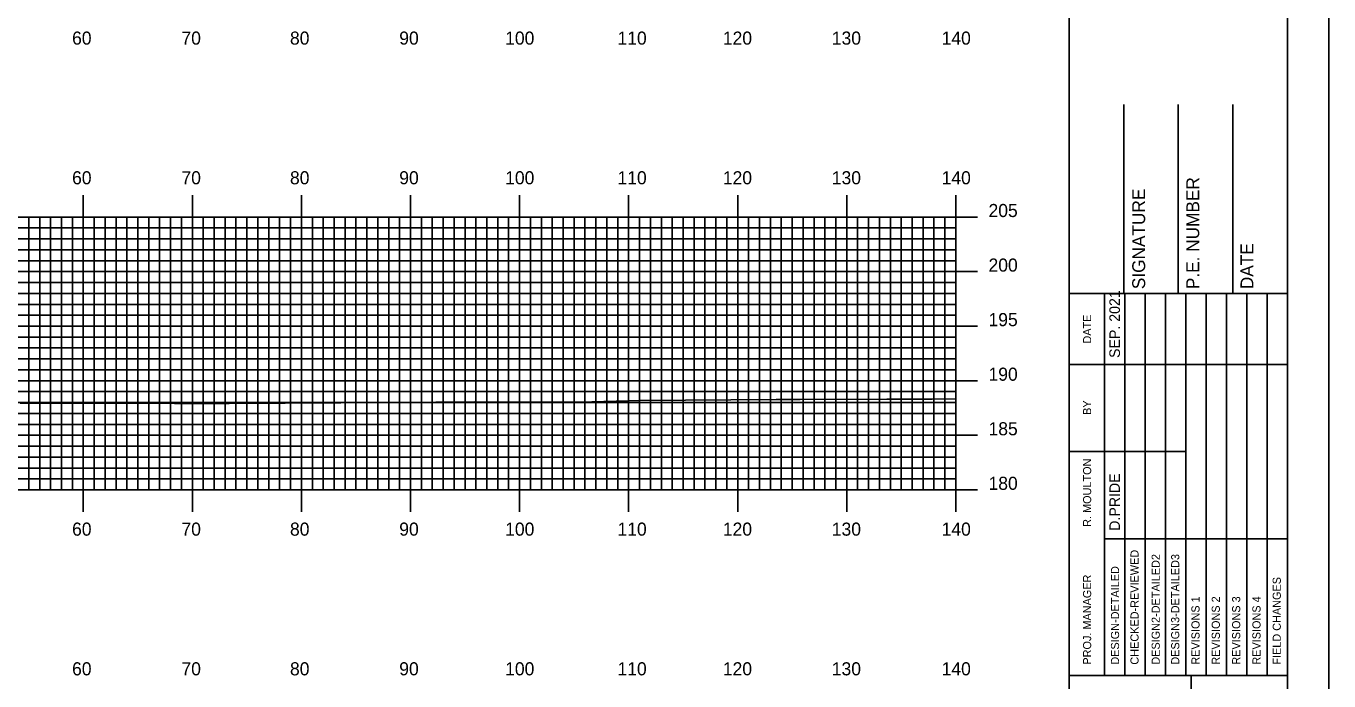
# Model space of a CAD drawing. Extents: x 1822392 to 1822735, y 442591 to 442811.
# Drawn here: x 1822612.5 to 1822732, y 442686.2 to 442746.2 of the extents above; entities that cross this region are included whole.
import ezdxf

# ---------------------------------------------------------------- set-up
doc = ezdxf.new("R2010")
doc.units = 0
for name, color, linetype in [('BORDER', 7, 'Continuous'), ('H_V ANNOTATION', 7, 'Continuous'), ('MAJOR', 7, 'Continuous'), ('MINOR', 7, 'Continuous'), ('PLOT BOUNDARY', 7, 'Continuous'), ('S_Roadway_Centerline', 7, 'Continuous')]:
    doc.layers.add(name, color=color, linetype=linetype)

msp = doc.modelspace()

# ---------------------------------------------------------------- linework, layer by layer
at = {"layer": 'BORDER'}
for p, q in [((1822708.17, 442596.67), (1822708.17, 442806.67)), ((1822713.17, 442721.67), (1822713.17, 442738.97)), ((1822718.17, 442721.67), (1822718.17, 442738.97)), ((1822723.17, 442721.67), (1822723.17, 442738.97)), ((1822708.17, 442721.67), (1822728.17, 442721.67)), ((1822708.17, 442686.67), (1822728.17, 442686.67)), ((1822719.35, 442616.67), (1822719.35, 442686.67))]:
    msp.add_line(p, q, dxfattribs=at)
msp.add_lwpolyline([(1822408.17, 442596.67), (1822728.17, 442596.67), (1822728.17, 442806.67), (1822408.17, 442806.67)], close=True, dxfattribs=at)
for points in [[(1822711.4, 442715.17), (1822711.4, 442721.67)], [(1822713.26, 442686.68), (1822713.26, 442721.67)], [(1822715.13, 442721.67), (1822715.13, 442686.68)], [(1822716.99, 442686.68), (1822716.99, 442721.67)], [(1822718.85, 442686.68), (1822718.85, 442721.67)], [(1822720.72, 442686.68), (1822720.72, 442721.67)], [(1822722.58, 442686.68), (1822722.58, 442721.67)], [(1822724.44, 442686.68), (1822724.44, 442721.67)], [(1822726.31, 442686.68), (1822726.31, 442721.67)], [(1822711.4, 442686.68), (1822711.4, 442720.26)], [(1822708.17, 442715.17), (1822728.17, 442715.17)], [(1822708.17, 442707.17), (1822711.4, 442707.17)], [(1822711.4, 442707.17), (1822718.85, 442707.17)], [(1822711.4, 442699.17), (1822728.17, 442699.17)]]:
    msp.add_lwpolyline(points, dxfattribs=at)
at = {"layer": 'MAJOR'}
for p, q in [((1822617.77, 442730.67), (1822617.77, 442728.67)), ((1822627.77, 442730.67), (1822627.77, 442728.67)), ((1822637.77, 442730.67), (1822637.77, 442728.67)), ((1822647.77, 442730.67), (1822647.77, 442728.67)), ((1822657.77, 442730.67), (1822657.77, 442728.67)), ((1822667.77, 442730.67), (1822667.77, 442728.67)), ((1822677.77, 442730.67), (1822677.77, 442728.67)), ((1822687.77, 442730.67), (1822687.77, 442728.67)), ((1822697.77, 442730.67), (1822697.77, 442728.67)), ((1822417.77, 442728.67), (1822697.77, 442728.67)), ((1822417.77, 442728.67), (1822697.77, 442728.67)), ((1822617.77, 442703.67), (1822617.77, 442728.67)), ((1822627.77, 442703.67), (1822627.77, 442728.67)), ((1822637.77, 442703.67), (1822637.77, 442728.67)), ((1822647.77, 442703.67), (1822647.77, 442728.67)), ((1822657.77, 442703.67), (1822657.77, 442728.67)), ((1822667.77, 442703.67), (1822667.77, 442728.67)), ((1822677.77, 442703.67), (1822677.77, 442728.67)), ((1822687.77, 442703.67), (1822687.77, 442728.67)), ((1822699.77, 442728.67), (1822695.77, 442728.67)), ((1822697.77, 442703.67), (1822697.77, 442728.67)), ((1822697.77, 442703.67), (1822697.77, 442728.67)), ((1822417.77, 442723.67), (1822697.77, 442723.67)), ((1822699.77, 442723.67), (1822695.77, 442723.67)), ((1822417.77, 442718.67), (1822697.77, 442718.67)), ((1822699.77, 442718.67), (1822695.77, 442718.67)), ((1822417.77, 442713.67), (1822697.77, 442713.67)), ((1822699.77, 442713.67), (1822695.77, 442713.67)), ((1822417.77, 442708.67), (1822697.77, 442708.67)), ((1822699.77, 442708.67), (1822695.77, 442708.67)), ((1822417.77, 442703.67), (1822697.77, 442703.67)), ((1822417.77, 442703.67), (1822697.77, 442703.67)), ((1822617.77, 442701.66), (1822617.77, 442703.67)), ((1822627.77, 442701.66), (1822627.77, 442703.67)), ((1822637.77, 442701.66), (1822637.77, 442703.67)), ((1822647.77, 442701.66), (1822647.77, 442703.67)), ((1822657.77, 442701.66), (1822657.77, 442703.67)), ((1822667.77, 442701.66), (1822667.77, 442703.67)), ((1822677.77, 442701.66), (1822677.77, 442703.67)), ((1822687.77, 442701.66), (1822687.77, 442703.67)), ((1822699.77, 442703.67), (1822695.77, 442703.67)), ((1822697.77, 442701.66), (1822697.77, 442703.67))]:
    msp.add_line(p, q, dxfattribs=at)
at = {"layer": 'MINOR'}
for p, q in [((1822612.77, 442703.67), (1822612.77, 442728.67)), ((1822613.77, 442703.67), (1822613.77, 442728.67)), ((1822614.77, 442703.67), (1822614.77, 442728.67)), ((1822615.77, 442703.67), (1822615.77, 442728.67)), ((1822616.77, 442703.67), (1822616.77, 442728.67)), ((1822618.77, 442703.67), (1822618.77, 442728.67)), ((1822619.77, 442703.67), (1822619.77, 442728.67)), ((1822620.77, 442703.67), (1822620.77, 442728.67)), ((1822621.77, 442703.67), (1822621.77, 442728.67)), ((1822622.77, 442703.67), (1822622.77, 442728.67)), ((1822623.77, 442703.67), (1822623.77, 442728.67)), ((1822624.77, 442703.67), (1822624.77, 442728.67)), ((1822625.77, 442703.67), (1822625.77, 442728.67)), ((1822626.77, 442703.67), (1822626.77, 442728.67)), ((1822628.77, 442703.67), (1822628.77, 442728.67)), ((1822629.77, 442703.67), (1822629.77, 442728.67)), ((1822630.77, 442703.67), (1822630.77, 442728.67)), ((1822631.77, 442703.67), (1822631.77, 442728.67)), ((1822632.77, 442703.67), (1822632.77, 442728.67)), ((1822633.77, 442703.67), (1822633.77, 442728.67)), ((1822634.77, 442703.67), (1822634.77, 442728.67)), ((1822635.77, 442703.67), (1822635.77, 442728.67)), ((1822636.77, 442703.67), (1822636.77, 442728.67)), ((1822638.77, 442703.67), (1822638.77, 442728.67)), ((1822639.77, 442703.67), (1822639.77, 442728.67)), ((1822640.77, 442703.67), (1822640.77, 442728.67)), ((1822641.77, 442703.67), (1822641.77, 442728.67)), ((1822642.77, 442703.67), (1822642.77, 442728.67)), ((1822643.77, 442703.67), (1822643.77, 442728.67)), ((1822644.77, 442703.67), (1822644.77, 442728.67)), ((1822645.77, 442703.67), (1822645.77, 442728.67)), ((1822646.77, 442703.67), (1822646.77, 442728.67)), ((1822648.77, 442703.67), (1822648.77, 442728.67)), ((1822649.77, 442703.67), (1822649.77, 442728.67)), ((1822650.77, 442703.67), (1822650.77, 442728.67)), ((1822651.77, 442703.67), (1822651.77, 442728.67)), ((1822652.77, 442703.67), (1822652.77, 442728.67)), ((1822653.77, 442703.67), (1822653.77, 442728.67)), ((1822654.77, 442703.67), (1822654.77, 442728.67)), ((1822655.77, 442703.67), (1822655.77, 442728.67)), ((1822656.77, 442703.67), (1822656.77, 442728.67)), ((1822658.77, 442703.67), (1822658.77, 442728.67)), ((1822659.77, 442703.67), (1822659.77, 442728.67)), ((1822660.77, 442703.67), (1822660.77, 442728.67)), ((1822661.77, 442703.67), (1822661.77, 442728.67)), ((1822662.77, 442703.67), (1822662.77, 442728.67)), ((1822663.77, 442703.67), (1822663.77, 442728.67)), ((1822664.77, 442703.67), (1822664.77, 442728.67)), ((1822665.77, 442703.67), (1822665.77, 442728.67)), ((1822666.77, 442703.67), (1822666.77, 442728.67)), ((1822668.77, 442703.67), (1822668.77, 442728.67)), ((1822669.77, 442703.67), (1822669.77, 442728.67)), ((1822670.77, 442703.67), (1822670.77, 442728.67)), ((1822671.77, 442703.67), (1822671.77, 442728.67)), ((1822672.77, 442703.67), (1822672.77, 442728.67)), ((1822673.77, 442703.67), (1822673.77, 442728.67)), ((1822674.77, 442703.67), (1822674.77, 442728.67)), ((1822675.77, 442703.67), (1822675.77, 442728.67)), ((1822676.77, 442703.67), (1822676.77, 442728.67)), ((1822678.77, 442703.67), (1822678.77, 442728.67)), ((1822679.77, 442703.67), (1822679.77, 442728.67)), ((1822680.77, 442703.67), (1822680.77, 442728.67)), ((1822681.77, 442703.67), (1822681.77, 442728.67)), ((1822682.77, 442703.67), (1822682.77, 442728.67)), ((1822683.77, 442703.67), (1822683.77, 442728.67)), ((1822684.77, 442703.67), (1822684.77, 442728.67)), ((1822685.77, 442703.67), (1822685.77, 442728.67)), ((1822686.77, 442703.67), (1822686.77, 442728.67)), ((1822688.77, 442703.67), (1822688.77, 442728.67)), ((1822689.77, 442703.67), (1822689.77, 442728.67)), ((1822690.77, 442703.67), (1822690.77, 442728.67)), ((1822691.77, 442703.67), (1822691.77, 442728.67)), ((1822692.77, 442703.67), (1822692.77, 442728.67)), ((1822693.77, 442703.67), (1822693.77, 442728.67)), ((1822694.77, 442703.67), (1822694.77, 442728.67)), ((1822695.77, 442703.67), (1822695.77, 442728.67)), ((1822696.77, 442703.67), (1822696.77, 442728.67)), ((1822417.77, 442727.67), (1822697.77, 442727.67)), ((1822697.77, 442727.67), (1822695.77, 442727.67)), ((1822417.77, 442726.67), (1822697.77, 442726.67)), ((1822697.77, 442726.67), (1822695.77, 442726.67)), ((1822417.77, 442725.67), (1822697.77, 442725.67)), ((1822697.77, 442725.67), (1822695.77, 442725.67)), ((1822417.77, 442724.67), (1822697.77, 442724.67)), ((1822697.77, 442724.67), (1822695.77, 442724.67)), ((1822417.77, 442722.67), (1822697.77, 442722.67)), ((1822697.77, 442722.67), (1822695.77, 442722.67)), ((1822417.77, 442721.67), (1822697.77, 442721.67)), ((1822697.77, 442721.67), (1822695.77, 442721.67)), ((1822417.77, 442720.67), (1822697.77, 442720.67)), ((1822697.77, 442720.67), (1822695.77, 442720.67)), ((1822417.77, 442719.67), (1822697.77, 442719.67)), ((1822697.77, 442719.67), (1822695.77, 442719.67)), ((1822417.77, 442717.67), (1822697.77, 442717.67)), ((1822417.77, 442716.67), (1822697.77, 442716.67)), ((1822697.77, 442717.67), (1822695.77, 442717.67)), ((1822697.77, 442716.67), (1822695.77, 442716.67)), ((1822417.77, 442715.67), (1822697.77, 442715.67)), ((1822697.77, 442715.67), (1822695.77, 442715.67)), ((1822417.77, 442714.67), (1822697.77, 442714.67)), ((1822697.77, 442714.67), (1822695.77, 442714.67)), ((1822417.77, 442712.67), (1822697.77, 442712.67)), ((1822697.77, 442712.67), (1822695.77, 442712.67)), ((1822417.77, 442711.67), (1822697.77, 442711.67)), ((1822697.77, 442711.67), (1822695.77, 442711.67)), ((1822417.77, 442710.67), (1822697.77, 442710.67)), ((1822417.77, 442709.67), (1822697.77, 442709.67)), ((1822697.77, 442710.67), (1822695.77, 442710.67)), ((1822697.77, 442709.67), (1822695.77, 442709.67)), ((1822417.77, 442707.67), (1822697.77, 442707.67)), ((1822697.77, 442707.67), (1822695.77, 442707.67)), ((1822417.77, 442706.67), (1822697.77, 442706.67)), ((1822697.77, 442706.67), (1822695.77, 442706.67)), ((1822417.77, 442705.67), (1822697.77, 442705.67)), ((1822697.77, 442705.67), (1822695.77, 442705.67)), ((1822417.77, 442704.67), (1822697.77, 442704.67)), ((1822697.77, 442704.67), (1822695.77, 442704.67))]:
    msp.add_line(p, q, dxfattribs=at)
at = {"layer": 'PLOT BOUNDARY'}
msp.add_lwpolyline([(1822391.98, 442590.55), (1822731.98, 442590.55), (1822731.98, 442810.55), (1822391.98, 442810.55)], close=True, dxfattribs=at)
at = {"layer": 'S_Roadway_Centerline'}
msp.add_lwpolyline([(1822611.99, 442711.6), (1822626.12, 442711.58), (1822629.87, 442711.59), (1822631.14, 442711.59), (1822646.53, 442711.68), (1822653.66, 442711.73), (1822663.31, 442711.72), (1822668.82, 442711.87), (1822681.31, 442711.96), (1822683.5, 442711.95), (1822691.46, 442711.97), (1822695.59, 442711.97), (1822697.77, 442712.01)], dxfattribs=at)

# ---------------------------------------------------------------- texts
at = {"layer": 'BORDER'}
for s, height, p in [('P.E. NUMBER', 1.1811, (1822720.09, 442722.06)), ('SIGNATURE', 1.181, (1822715.13, 442722.06)), ('DATE', 1.181, (1822725.05, 442722.06)), ('SEP. 2021', 0.969, (1822712.82, 442715.76)), ('DATE', 0.743, (1822710.18, 442717.08)), ('BY', 0.743, (1822710.18, 442710.54)), ('R. MOULTON', 0.745, (1822710.18, 442700.28)), ('D.PRIDE', 0.969, (1822712.82, 442699.92)), ('CHECKED-REVIEWED', 0.7455, (1822714.53, 442687.65)), ('DESIGN2-DETAILED2', 0.7455, (1822716.47, 442687.65)), ('DESIGN3-DETAILED3', 0.7455, (1822718.26, 442687.65)), ('DESIGN-DETAILED', 0.7455, (1822712.74, 442687.65)), ('PROJ. MANAGER', 0.7455, (1822710.18, 442687.65)), ('FIELD CHANGES', 0.7455, (1822727.57, 442687.65)), ('REVISIONS 1', 0.7455, (1822720.12, 442687.65)), ('REVISIONS 2', 0.7455, (1822721.98, 442687.65)), ('REVISIONS 3', 0.7455, (1822723.85, 442687.65)), ('REVISIONS 4', 0.7455, (1822725.71, 442687.65))]:
    msp.add_text(s, height=height, rotation=90, dxfattribs=at).set_placement(p)
at = {"layer": 'H_V ANNOTATION'}
for s, p in [('60', (1822616.74, 442744.47)), ('70', (1822626.77, 442744.47)), ('80', (1822636.72, 442744.47)), ('90', (1822646.74, 442744.47)), ('100', (1822656.45, 442744.47)), ('110', (1822666.75, 442744.47)), ('120', (1822676.41, 442744.47)), ('130', (1822686.4, 442744.47)), ('140', (1822696.47, 442744.47)), ('60', (1822616.74, 442731.67)), ('70', (1822626.77, 442731.67)), ('80', (1822636.72, 442731.67)), ('90', (1822646.74, 442731.67)), ('100', (1822656.45, 442731.67)), ('110', (1822666.75, 442731.67)), ('120', (1822676.41, 442731.67)), ('130', (1822686.4, 442731.67)), ('140', (1822696.47, 442731.67)), ('205', (1822700.77, 442728.67)), ('200', (1822700.77, 442723.67)), ('195', (1822700.77, 442718.67)), ('190', (1822700.77, 442713.67)), ('185', (1822700.77, 442708.67)), ('180', (1822700.77, 442703.67)), ('60', (1822616.74, 442699.47)), ('70', (1822626.77, 442699.47)), ('80', (1822636.72, 442699.47)), ('90', (1822646.74, 442699.47)), ('100', (1822656.45, 442699.47)), ('110', (1822666.75, 442699.47)), ('120', (1822676.41, 442699.47)), ('130', (1822686.4, 442699.47)), ('140', (1822696.47, 442699.47)), ('60', (1822616.74, 442686.67)), ('70', (1822626.77, 442686.67)), ('80', (1822636.72, 442686.67)), ('90', (1822646.74, 442686.67)), ('100', (1822656.45, 442686.67)), ('110', (1822666.75, 442686.67)), ('120', (1822676.41, 442686.67)), ('130', (1822686.4, 442686.67)), ('140', (1822696.47, 442686.67))]:
    msp.add_text(s, height=1.2, dxfattribs=at).set_placement(p)

doc.saveas('drawing.dxf')
